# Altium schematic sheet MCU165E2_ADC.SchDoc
size 431 x 279 mm; Date: Not shown in title block; ApprovedBy: Not shown in title block; CheckedBy: Not shown in title block; Author: Not shown in title block; CompanyName: Not shown in title block; Engineer: Not shown in title block; Organization: Not shown in title block; Address1: Not shown in title block; Address2: Not shown in title block; Address3: Not shown in title block; Address4: Not shown in title block; DocumentNumber: 5; Revision: Use project parameter SCH_Rev; SheetNumber: 5; SheetTotal: 10; PageSetup: Record=PageOptions¦CenterHorizontal=True¦CenterVertical=True¦PrintScale=1.00¦XCorrection=1.00¦YCorrection=1.00¦PrintKind=0¦BorderSize=5000000¦LeftOffset=0¦BottomOffset=0¦Orientation=2¦PaperLength=1000¦PaperWidth=1000¦Scale=100¦PaperSource=15¦PrintQuality=600¦MediaType=1¦DitherType=10¦PaperKind=Letter¦PrintScaleMode=1
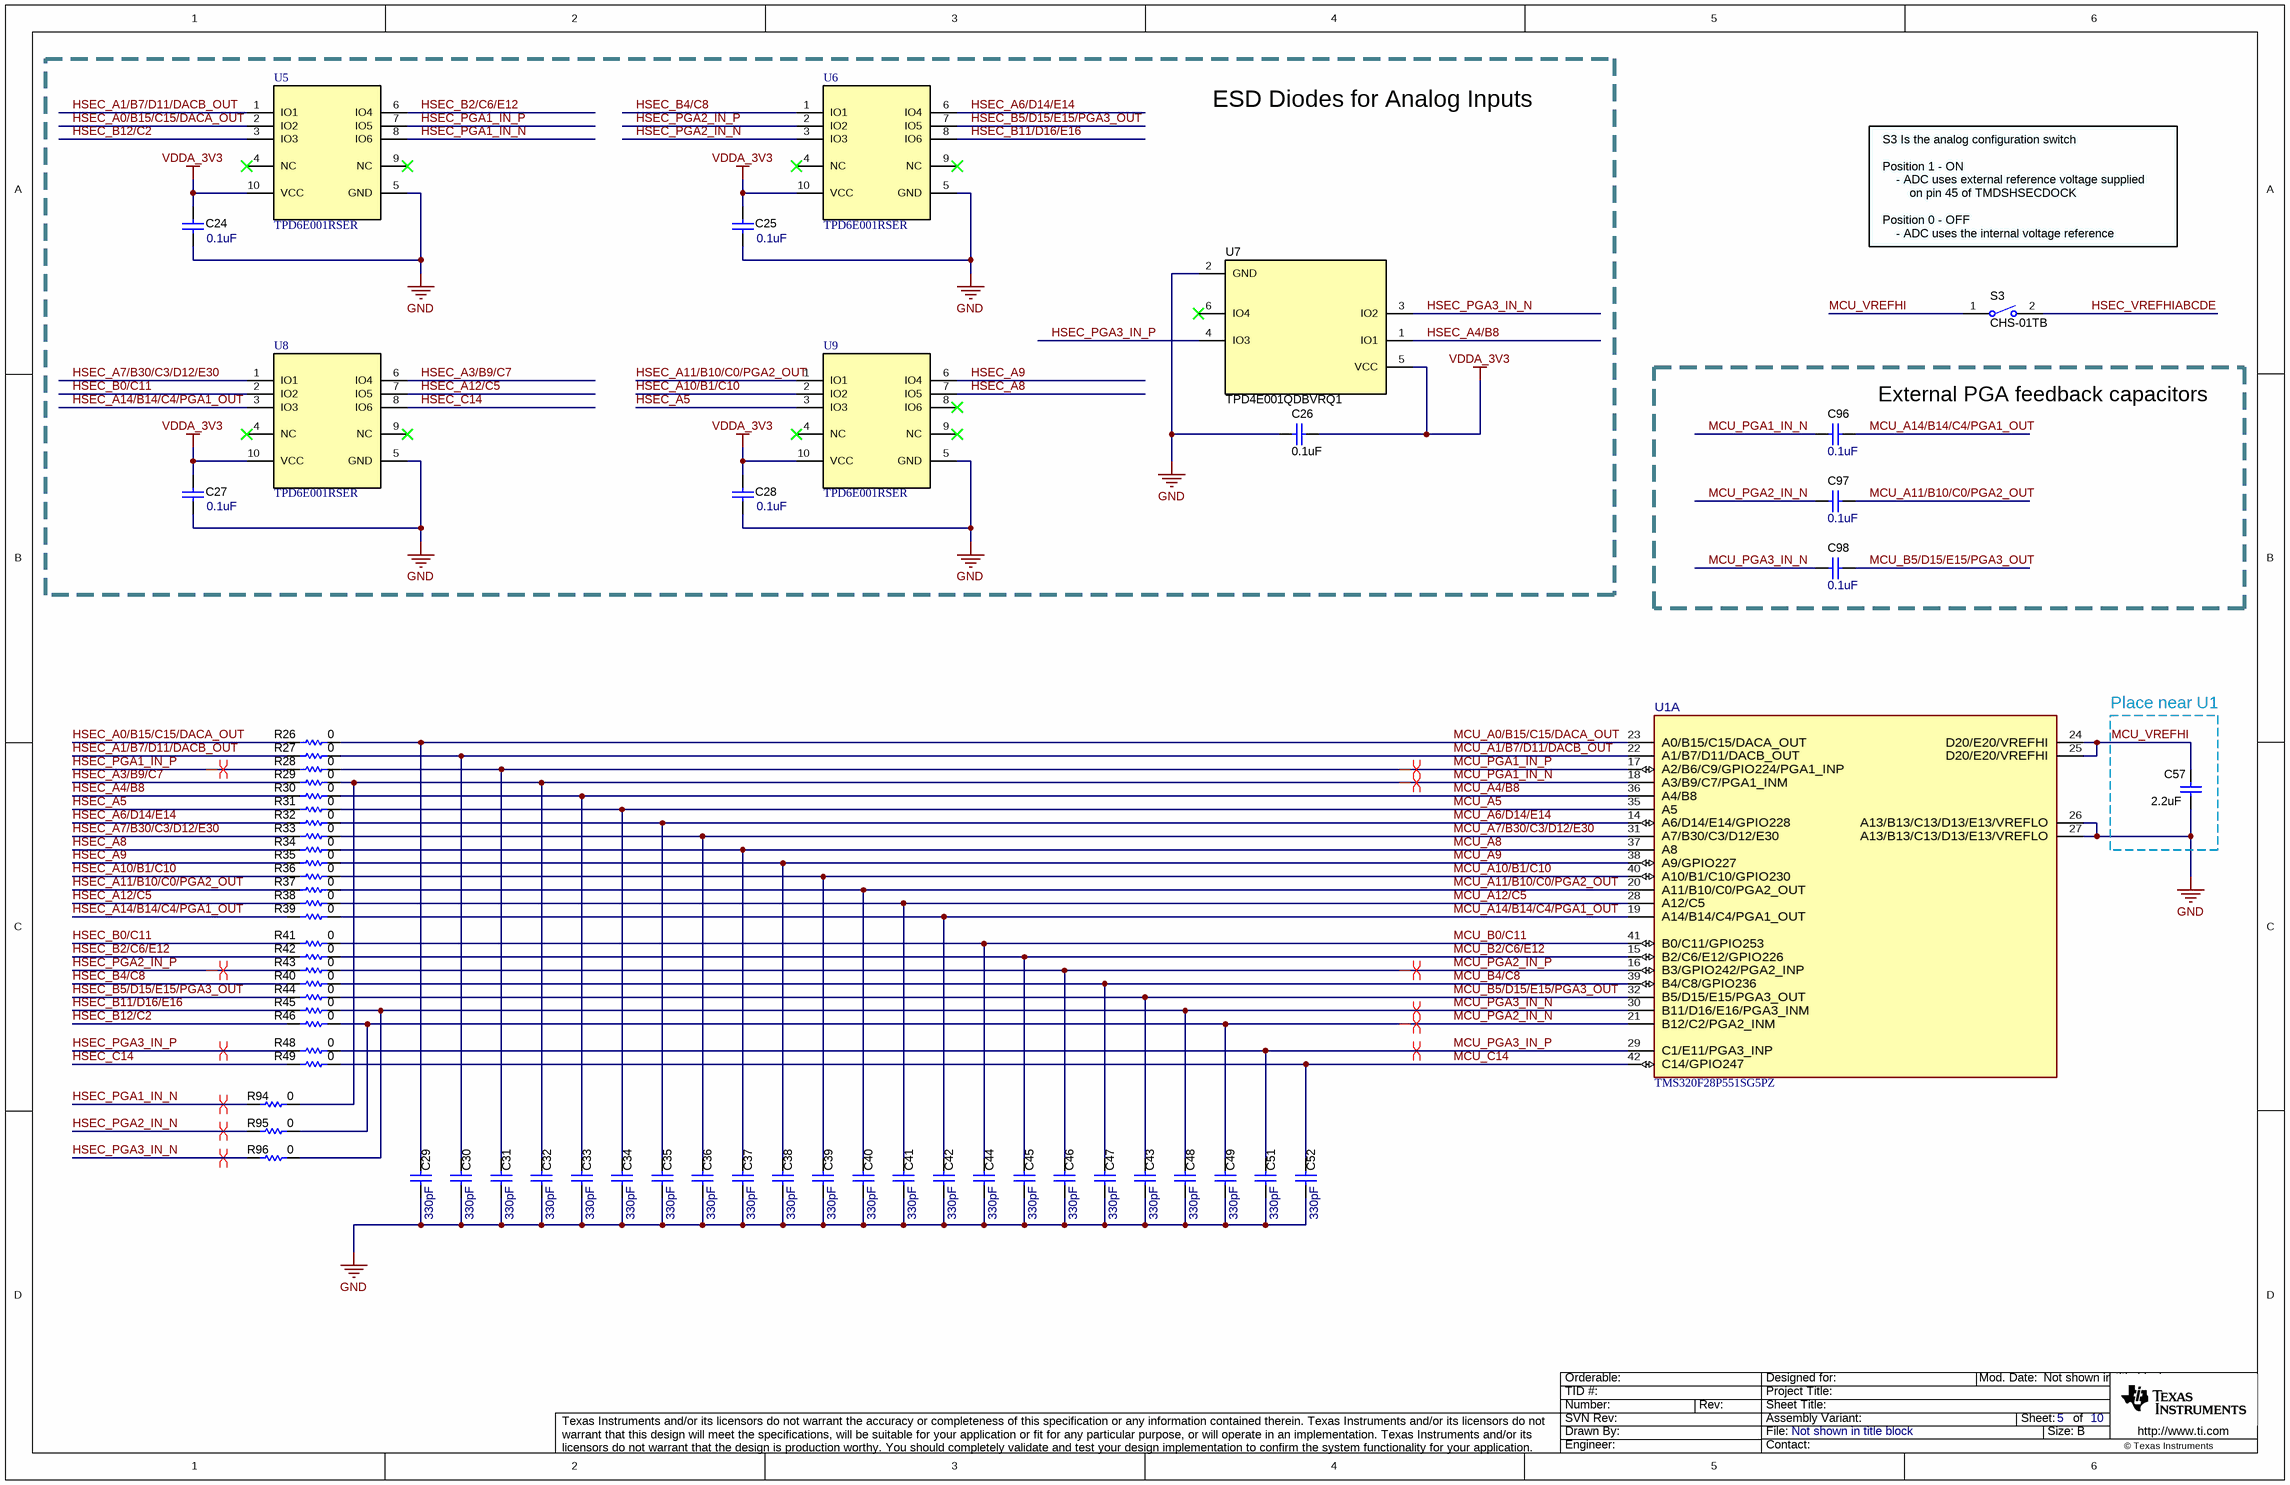
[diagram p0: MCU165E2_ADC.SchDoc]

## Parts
C24  Cap_F: 0.1uF  [0603]  (hidden comment: 885012206046)
C25  Cap_F: 0.1uF  [0603]  (hidden comment: 885012206046)
C26  ValueDisplayed: 0.1uF  [0603]  (hidden comment: C0603C104K8RACTU)
C27  Cap_F: 0.1uF  [0603]  (hidden comment: 885012206046)
C28  Cap_F: 0.1uF  [0603]  (hidden comment: 885012206046)
C29  ValueDisplayed: 330pF  [0603]  (hidden comment: C0603C331J5GACTU)
C30  ValueDisplayed: 330pF  [0603]  (hidden comment: C0603C331J5GACTU)
C31  ValueDisplayed: 330pF  [0603]  (hidden comment: C0603C331J5GACTU)
C32  ValueDisplayed: 330pF  [0603]  (hidden comment: C0603C331J5GACTU)
C33  ValueDisplayed: 330pF  [0603]  (hidden comment: C0603C331J5GACTU)
C34  ValueDisplayed: 330pF  [0603]  (hidden comment: C0603C331J5GACTU)
C35  ValueDisplayed: 330pF  [0603]  (hidden comment: C0603C331J5GACTU)
C36  ValueDisplayed: 330pF  [0603]  (hidden comment: C0603C331J5GACTU)
C37  ValueDisplayed: 330pF  [0603]  (hidden comment: C0603C331J5GACTU)
C38  ValueDisplayed: 330pF  [0603]  (hidden comment: C0603C331J5GACTU)
C39  ValueDisplayed: 330pF  [0603]  (hidden comment: C0603C331J5GACTU)
C40  ValueDisplayed: 330pF  [0603]  (hidden comment: C0603C331J5GACTU)
C41  ValueDisplayed: 330pF  [0603]  (hidden comment: C0603C331J5GACTU)
C42  ValueDisplayed: 330pF  [0603]  (hidden comment: C0603C331J5GACTU)
C43  ValueDisplayed: 330pF  [0603]  (hidden comment: C0603C331J5GACTU)
C44  ValueDisplayed: 330pF  [0603]  (hidden comment: C0603C331J5GACTU)
C45  ValueDisplayed: 330pF  [0603]  (hidden comment: C0603C331J5GACTU)
C46  ValueDisplayed: 330pF  [0603]  (hidden comment: C0603C331J5GACTU)
C47  ValueDisplayed: 330pF  [0603]  (hidden comment: C0603C331J5GACTU)
C48  ValueDisplayed: 330pF  [0603]  (hidden comment: C0603C331J5GACTU)
C49  ValueDisplayed: 330pF  [0603]  (hidden comment: C0603C331J5GACTU)
C51  ValueDisplayed: 330pF  [0603]  (hidden comment: C0603C331J5GACTU)
C52  ValueDisplayed: 330pF  [0603]  (hidden comment: C0603C331J5GACTU)
C57  ValueDisplayed: 2.2uF  [0603]  (hidden comment: 885012106018)
C96  Cap_F: 0.1uF  [0603]  (hidden comment: 885012206046)
C97  Cap_F: 0.1uF  [0603]  (hidden comment: 885012206046)
C98  Cap_F: 0.1uF  [0603]  (hidden comment: 885012206046)
R26  ValueDisplayed: 0  [0603]  (hidden comment: CRCW06030000Z0EA)
R27  ValueDisplayed: 0  [0603]  (hidden comment: CRCW06030000Z0EA)
R28  ValueDisplayed: 0  [0603]  (hidden comment: CRCW06030000Z0EA)
R29  ValueDisplayed: 0  [0603]  (hidden comment: CRCW06030000Z0EA)
R30  ValueDisplayed: 0  [0603]  (hidden comment: CRCW06030000Z0EA)
R31  ValueDisplayed: 0  [0603]  (hidden comment: CRCW06030000Z0EA)
R32  ValueDisplayed: 0  [0603]  (hidden comment: CRCW06030000Z0EA)
R33  ValueDisplayed: 0  [0603]  (hidden comment: CRCW06030000Z0EA)
R34  ValueDisplayed: 0  [0603]  (hidden comment: CRCW06030000Z0EA)
R35  ValueDisplayed: 0  [0603]  (hidden comment: CRCW06030000Z0EA)
R36  ValueDisplayed: 0  [0603]  (hidden comment: CRCW06030000Z0EA)
R37  ValueDisplayed: 0  [0603]  (hidden comment: CRCW06030000Z0EA)
R38  ValueDisplayed: 0  [0603]  (hidden comment: CRCW06030000Z0EA)
R39  ValueDisplayed: 0  [0603]  (hidden comment: CRCW06030000Z0EA)
R40  ValueDisplayed: 0  [0603]  (hidden comment: CRCW06030000Z0EA)
R41  ValueDisplayed: 0  [0603]  (hidden comment: CRCW06030000Z0EA)
R42  ValueDisplayed: 0  [0603]  (hidden comment: CRCW06030000Z0EA)
R43  ValueDisplayed: 0  [0603]  (hidden comment: CRCW06030000Z0EA)
R44  ValueDisplayed: 0  [0603]  (hidden comment: CRCW06030000Z0EA)
R45  ValueDisplayed: 0  [0603]  (hidden comment: CRCW06030000Z0EA)
R46  ValueDisplayed: 0  [0603]  (hidden comment: CRCW06030000Z0EA)
R48  ValueDisplayed: 0  [0603]  (hidden comment: CRCW06030000Z0EA)
R49  ValueDisplayed: 0  [0603]  (hidden comment: CRCW06030000Z0EA)
R94  ValueDisplayed: 0  [0603]  (hidden comment: CRCW06030000Z0EA)
R95  ValueDisplayed: 0  [0603]  (hidden comment: CRCW06030000Z0EA)
R96  ValueDisplayed: 0  [0603]  (hidden comment: CRCW06030000Z0EA)
S3  CHS-01TB  [SW_CHS-01TB]
U1  TMS320F28P551SG5PZ  [PZ0100A-MFG]  (part A of 4)
U5  TPD6E001RSER  [RSE0010A]
U6  TPD6E001RSER  [RSE0010A]
U7  TPD4E001QDBVRQ1  [DBV0006A_N]
U8  TPD6E001RSER  [RSE0010A]
U9  TPD6E001RSER  [RSE0010A]

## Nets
GND: C24.2 C25.2 C26.1 C27.2 C28.2 C29.2 C30.2 C31.2 C32.2 C33.2 C34.2 C35.2 C36.2 C37.2 C38.2 C39.2 C40.2 C41.2 C42.2 C43.2 C44.2 C45.2 C46.2 C47.2 C48.2 C49.2 C51.2 C52.2 C57.2 U1.26(A13/B13/C13/D13/E13/VREFLO) U1.27(A13/B13/C13/D13/E13/VREFLO) U5.5(GND) U6.5(GND) U7.2(GND) U8.5(GND) U9.5(GND)
VDDA_3V3: C24.1 C25.1 C26.2 C27.1 C28.1 U5.10(VCC) U6.10(VCC) U7.5(VCC) U8.10(VCC) U9.10(VCC)
HSEC_A0/B15/C15/DACA_OUT: R26.2 U5.2(IO2)
HSEC_A1/B7/D11/DACB_OUT: R27.2 U5.1(IO1)
HSEC_A3/B9/C7: R29.2 U8.6(IO4)
HSEC_A4/B8: R30.2 U7.1(IO1)
HSEC_A5: R31.2 U9.3(IO3)
HSEC_A6/D14/E14: R32.2 U6.6(IO4)
HSEC_A7/B30/C3/D12/E30: R33.2 U8.1(IO1)
HSEC_A8: R34.2 U9.7(IO5)
HSEC_A9: R35.2 U9.6(IO4)
HSEC_A10/B1/C10: R36.2 U9.2(IO2)
HSEC_A11/B10/C0/PGA2_OUT: R37.2 U9.1(IO1)
HSEC_A12/C5: R38.2 U8.7(IO5)
HSEC_A14/B14/C4/PGA1_OUT: R39.2 U8.3(IO3)
HSEC_B0/C11: R41.2 U8.2(IO2)
HSEC_B2/C6/E12: R42.2 U5.6(IO4)
HSEC_B4/C8: R40.2 U6.1(IO1)
HSEC_B5/D15/E15/PGA3_OUT: R44.2 U6.7(IO5)
HSEC_B11/D16/E16: R45.2 U6.8(IO6)
HSEC_B12/C2: R46.2 U5.3(IO3)
HSEC_C14: R49.2 U8.8(IO6)
HSEC_PGA1_IN_N: R94.2 U5.8(IO6)
HSEC_PGA1_IN_P: R28.2 U5.7(IO5)
HSEC_PGA2_IN_N: R95.2 U6.3(IO3)
HSEC_PGA2_IN_P: R43.2 U6.2(IO2)
HSEC_PGA3_IN_N: R96.2 U7.3(IO2)
HSEC_PGA3_IN_P: R48.2 U7.4(IO3)
HSEC_VREFHIABCDE: S3.2
MCU_A0/B15/C15/DACA_OUT: C29.1 R26.1 U1.23(A0/B15/C15/DACA_OUT)
MCU_A1/B7/D11/DACB_OUT: C30.1 R27.1 U1.22(A1/B7/D11/DACB_OUT)
MCU_A4/B8: C33.1 R30.1 U1.36(A4/B8)
MCU_A5: C34.1 R31.1 U1.35(A5)
MCU_A6/D14/E14: C35.1 R32.1 U1.14(A6/D14/E14/GPIO228)
MCU_A7/B30/C3/D12/E30: C36.1 R33.1 U1.31(A7/B30/C3/D12/E30)
MCU_A8: C37.1 R34.1 U1.37(A8)
MCU_A9: C38.1 R35.1 U1.38(A9/GPIO227)
MCU_A10/B1/C10: C39.1 R36.1 U1.40(A10/B1/C10/GPIO230)
MCU_A11/B10/C0/PGA2_OUT: C40.1 C97.2 R37.1 U1.20(A11/B10/C0/PGA2_OUT)
MCU_A12/C5: C41.1 R38.1 U1.28(A12/C5)
MCU_A14/B14/C4/PGA1_OUT: C42.1 C96.2 R39.1 U1.19(A14/B14/C4/PGA1_OUT)
MCU_B0/C11: C44.1 R41.1 U1.41(B0/C11/GPIO253)
MCU_B2/C6/E12: C45.1 R42.1 U1.15(B2/C6/E12/GPIO226)
MCU_B4/C8: C47.1 R40.1 U1.39(B4/C8/GPIO236)
MCU_B5/D15/E15/PGA3_OUT: C43.1 C98.2 R44.1 U1.32(B5/D15/E15/PGA3_OUT)
MCU_C14: C52.1 R49.1 U1.42(C14/GPIO247)
MCU_PGA1_IN_N: C32.1 C96.1 R29.1 R94.1 U1.18(A3/B9/C7/PGA1_INM)
MCU_PGA1_IN_P: C31.1 R28.1 U1.17(A2/B6/C9/GPIO224/PGA1_INP)
MCU_PGA2_IN_N: C49.1 C97.1 R46.1 R95.1 U1.21(B12/C2/PGA2_INM)
MCU_PGA2_IN_P: C46.1 R43.1 U1.16(B3/GPIO242/PGA2_INP)
MCU_PGA3_IN_N: C48.1 C98.1 R45.1 R96.1 U1.30(B11/D16/E16/PGA3_INM)
MCU_PGA3_IN_P: C51.1 R48.1 U1.29(C1/E11/PGA3_INP)
MCU_VREFHI: C57.1 S3.1 U1.24(D20/E20/VREFHI) U1.25(D20/E20/VREFHI)

Not connected (* = marked no-connect by the designer): U5 4(NC)* 9(NC)*; U6 4(NC)* 9(NC)*; U7 6(IO4)*; U8 4(NC)* 9(NC)*; U9 4(NC)* 8(IO6)* 9(NC)*

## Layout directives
differential pair: HSEC_PGA1_IN_N, HSEC_PGA1_IN_P, HSEC_PGA2_IN_N, HSEC_PGA2_IN_P, HSEC_PGA3_IN_N, HSEC_PGA3_IN_P, MCU_PGA1_IN_N, MCU_PGA1_IN_P, MCU_PGA2_IN_N, MCU_PGA2_IN_P, MCU_PGA3_IN_N, MCU_PGA3_IN_P

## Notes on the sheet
- ESD Diodes for Analog Inputs
- S3 Is the analog configuration switch
- Position 1 - ON
- Position 0 - OFF
- - ADC uses external reference voltage supplied
- - ADC uses the internal voltage reference
- on pin 45 of TMDSHSECDOCK
- (near C96) External PGA feedback capacitors
- Place near U1

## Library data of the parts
C24 C25 C27 C28 C96-C98 = CMP-0006829-4: CAP, CERM, 0.1 uF, 16 V, +/- 10%, X7R, 0603; Manufacturer: Wurth Elektronik; TaMin_C: -55°C; Polarized: N; SizeAreaWB_mm2: 4.68; Value1: Unknown; U/M: EA; Value: 0.1uF; TaMax_C: 125°C; SizeZ_mm: 1; SizeX_mm: 1.6; SizeY_mm: 0.8; Value2: 16V; SizeArea_mm2: 1.28; AEC Category: Q200
C26 = CMP-0006862-5: CAP, CERM, 0.1 uF, 10 V, +/- 10%, X7R, 0603; Manufacturer: Kemet; TaMin_C: -55°C; Polarized: N; SizeAreaWB_mm2: 4.68; Value1: Unknown; U/M: EA; Value: 0.1uF; TaMax_C: 125°C; SizeZ_mm: 1; SizeX_mm: 1.6; SizeY_mm: 0.8; Value2: 10V; SizeArea_mm2: 1.28; Cap_F: 100nF; AEC Category: Q200
C29-C49 C51 C52 = CMP-0006920-4: CAP, CERM, 330 pF, 50 V, +/- 5%, C0G/NP0, 0603; Manufacturer: Kemet; TaMin_C: -55°C; Polarized: N; SizeAreaWB_mm2: 4.68; Value1: Unknown; U/M: EA; Value: 330pF; TaMax_C: 125°C; SizeZ_mm: 1; SizeX_mm: 1.6; SizeY_mm: 0.8; Value2: 50V; SizeArea_mm2: 1.28; AEC Category: Q200
C57 = CMP-0006825-5: CAP, CERM, 2.2 uF, 16 V, +/- 20%, X5R, 0603; Manufacturer: Wurth Elektronik; TaMin_C: -55°C; Polarized: N; SizeAreaWB_mm2: 4.68; Value1: Unknown; U/M: EA; Value: 2.2uF; TaMax_C: 85°C; SizeZ_mm: 1; SizeX_mm: 1.6; SizeY_mm: 0.8; Value2: 16V; SizeArea_mm2: 1.28; Cap_F: 2.2µF; AEC Category: Q200
R26-R46 R48 R49 R94-R96 = CMP-0025697-4: RES, 0, 5%, 0.1 W, AEC-Q200 Grade 0, 0603; Manufacturer: Vishay-Dale; Value: 0; Value_Code: 0000; Power_W: 100mW; Value2: 0.1W; VDC_V: 75V; TempCo: 200 ppm/C; EIA_Code: E24; AEC Category: Q200; AEC Qualified: Y; SizeArea_mm2: 1.28; SizeX_mm: 1.6; SizeY_mm: 0.8; SizeZ_mm: 1
S3 = CMP-0002163-2: Switch, Slide, SPST, Top Slide, SMT; Manufacturer: Copal Electronics; CurrentRating_mA: 100A; SwitchFunction: Off-On; VDC_V: 6V; PositionCount: 1
U1 = CMP-0124912-2: Real-Time Microcontroller, LQFP100; Manufacturer: Texas Instruments; SizeZ_mm: 1.6mm; AEC Qualified: No; AEC Grade: NA; Core Architecture: C28x; Data Bus Width: 32bits; Frequency_Fixed: 160MHz; Interface: I2C,SPI,UART,CAN,LIN,SCI; Max Supply Voltage: 3.63V; Memory Size: 512KBytes; Memory Type: FLASH; Min Supply Voltage: 1.14V; Number Of A/D Converters: 5; Number Of Adc Channels: 35; Number Of Cores: 1; Number Of I/Os: 43; Number Of I2C Channels: 2; Number Of Pwm Channels: 24; Number Of Timers/Counters: 3; Ram Size: 101KBytes; Standoff Height: 0.05mm; TaMax_C: +125°C; TaMin_C: -40°C; TJmax_C: +150°C; AEC Category: Q200; CompType: IC
U5 U6 U8 U9 = CMP-0043123-1: Low-Capacitance + / - 15 kV ESD Protection Array for High-Speed Data Interfaces, 6 Channels, -40 to +85 degC, 10-pin UQFN (RSE), Green (RoHS & no Sb/Br); Manufacturer: Texas Instruments; Serial ATA / eSATA: TRUE; IO Leakage Current(nA): 1; IO Capacitance(Typ)(pF): 1.5; IEC 61000-4-2 Contact(+/- kV): 8; Breakdown Voltage(Min)(V): 11; IEC 61000-4-2 Air-Gap(+/- kV): 15; SubFamily: ESD Solution
U7 = CMP-0066599-1: Automotive Low-Capacitance 4-Channel +/-15-kV ESD Protection Array for High-Speed Data Interfaces, DBV0006A (SOT-23-6); Alternate Manufacturer: Texas Instruments; SizeAreaWB_mm2: 14.82; U/M: EA; SizeZ_mm: 1.45; SizeX_mm: 2.8; SizeY_mm: 2.9; SizeArea_mm2: 8.12; CompType: IC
